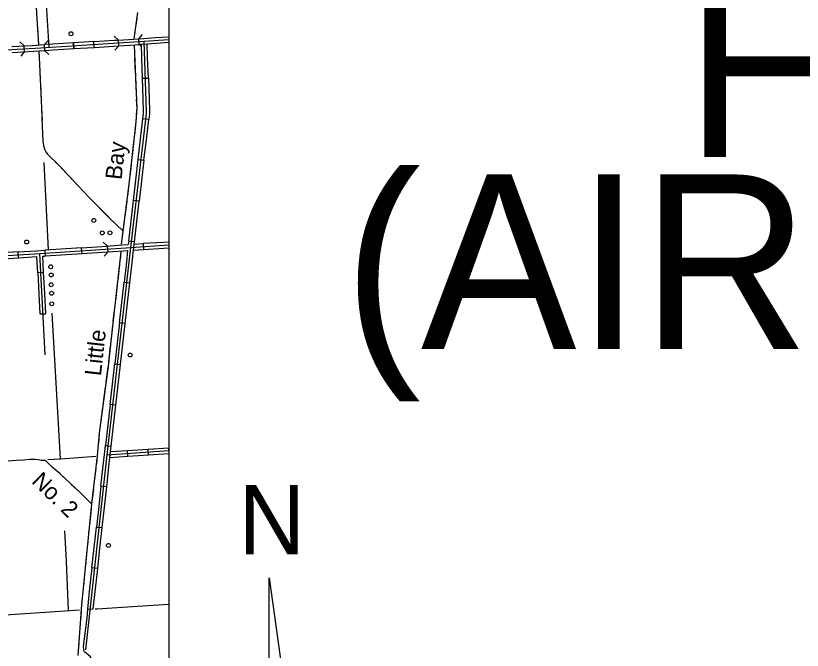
# Model space of a CAD drawing. Extents: x 309348 to 309445, y 336383 to 336484.
# Drawn here: x 309355.577 to 309359.624, y 336398.969 to 336402.233 of the extents above; entities that cross this region are included whole.
import ezdxf

# ---------------------------------------------------------------- set-up
doc = ezdxf.new("R2010")
doc.units = 0
doc.layers.add('R_Annotation', color=7, linetype='Continuous')
doc.layers.add('R_Border Notes', color=7, linetype='Continuous')

msp = doc.modelspace()

# ---------------------------------------------------------------- linework, layer by layer
at = {"layer": 'R_Annotation'}
for p, q in [((309356.107, 336402.0778), (309356.1051, 336402.1077)), ((309356.2116, 336402.0843), (309356.2097, 336402.1142)), ((309355.6221, 336402.0478), (309355.6203, 336402.0777)), ((309355.7231, 336402.0838), (309355.7248, 336402.0538)), ((309355.8754, 336402.0633), (309355.8735, 336402.0933)), ((309355.8735, 336402.0933), (309355.8754, 336402.0633)), ((309355.9808, 336402.0699), (309355.9789, 336402.0998)), ((309356.2106, 336402.0993), (309356.2106, 336402.0993)), ((309356.2116, 336402.0843), (309356.2116, 336402.0843)), ((309356.229, 336401.911), (309356.259, 336401.912)), ((309356.2611, 336401.6987), (309356.2313, 336401.7022)), ((309356.2068, 336401.4924), (309356.2366, 336401.4889)), ((309356.2122, 336401.2791), (309356.1824, 336401.2825)), ((309356.1877, 336401.0692), (309356.1579, 336401.0727)), ((309356.1828, 336401.0271), (309356.1863, 336401.0574)), ((309356.2321, 336401.0604), (309356.234, 336401.0304)), ((309355.5916, 336400.9879), (309355.5897, 336401.0178)), ((309355.8105, 336401.0322), (309355.7267, 336401.0266)), ((309355.7267, 336401.0266), (309355.7288, 336400.9973)), ((309355.9159, 336401.0393), (309355.8105, 336401.0322)), ((309355.9179, 336401.0093), (309355.9159, 336401.0393)), ((309356.0515, 336401.0183), (309356.0494, 336401.0483)), ((309356.0505, 336401.0333), (309356.0505, 336401.0333)), ((309355.7288, 336400.9973), (309355.9179, 336401.0093)), ((309355.72, 336400.9113), (309355.6901, 336400.9097)), ((309355.72, 336400.9113), (309355.72, 336400.9113)), ((309356.1339, 336400.8627), (309356.1637, 336400.8593)), ((309355.7013, 336400.6987), (309355.7312, 336400.7003)), ((309356.1398, 336400.6494), (309356.11, 336400.6528)), ((309356.0861, 336400.4429), (309356.1159, 336400.4395)), ((309356.092, 336400.2296), (309356.0622, 336400.233)), ((309356.092, 336400.2296), (309356.092, 336400.2296)), ((309356.0383, 336400.0231), (309356.0681, 336400.0197)), ((309356.2597, 336399.9738), (309356.2577, 336400.0037)), ((309356.3641, 336399.9968), (309356.3631, 336400.0108)), ((309356.1543, 336399.9668), (309356.1523, 336399.9967)), ((309356.0448, 336399.8097), (309356.015, 336399.813)), ((309355.9918, 336399.6031), (309356.0216, 336399.5998)), ((309355.9984, 336399.3898), (309355.9686, 336399.3931)), ((309356.8815, 336399.3417), (309357.1027, 336397.7428)), ((309356.8815, 336397.4244), (309356.8815, 336399.3417)), ((309355.9451, 336399.1806), (309355.9755, 336399.1826))]:
    msp.add_line(p, q, dxfattribs=at)
for points in [[(309355.6632, 336402.7078), (309355.679, 336402.3352), (309355.6875, 336402.1915), (309355.693, 336402.0854)], [(309355.7301, 336402.3468), (309355.7462, 336402.0701)], [(309356.2038, 336402.2495), (309356.1847, 336402.1141)], [(309355.6858, 336402.2198), (309355.6875, 336402.1915), (309355.6901, 336402.1407)], [(309356.1995, 336402.2191), (309356.1884, 336402.1406)], [(309354.9254, 336402.0215), (309355.1653, 336402.0358), (309355.7066, 336402.0678), (309356.2375, 336402.1009), (309356.3641, 336402.1095)], [(309355.6915, 336402.1143), (309355.693, 336402.0854)], [(309355.7231, 336402.0831), (309355.743, 336402.1056)], [(309355.9789, 336402.0998), (309356.0844, 336402.1064), (309356.1051, 336402.1077)], [(309356.0826, 336402.1276), (309356.1051, 336402.1077)], [(309356.1051, 336402.1077), (309356.2097, 336402.1142)], [(309356.1848, 336402.1145), (309356.1847, 336402.1141)], [(309356.2097, 336402.1142), (309356.2296, 336402.1367)], [(309356.2097, 336402.1142), (309356.2366, 336402.1159), (309356.2951, 336402.1199)], [(309356.2951, 336402.1199), (309356.3641, 336402.1245)], [(309355.5572, 336402.074), (309355.6627, 336402.0802)], [(309355.5979, 336402.0977), (309355.6203, 336402.0777)], [(309355.6627, 336402.0802), (309355.7231, 336402.0838)], [(309355.7681, 336402.0867), (309355.7231, 336402.0839)], [(309355.8735, 336402.0933), (309355.7681, 336402.0867)], [(309355.77, 336402.0567), (309355.8754, 336402.0633)], [(309355.9789, 336402.0998), (309355.8735, 336402.0933)], [(309355.8754, 336402.0633), (309355.9808, 336402.0699)], [(309355.9371, 336398.9714), (309356.0479, 336399.9747), (309356.1694, 336401.0413), (309356.2478, 336401.7142), (309356.2493, 336401.7307), (309356.2498, 336401.7404), (309356.2375, 336402.1009)], [(309355.9808, 336402.0699), (309356.107, 336402.0778)], [(309356.107, 336402.0778), (309356.0871, 336402.0553)], [(309356.107, 336402.0778), (309356.1917, 336402.083), (309356.2116, 336402.0843)], [(309356.1859, 336402.0808), (309356.199, 336401.7547), (309356.1947, 336401.6861), (309356.1593, 336401.3669), (309356.1286, 336401.1238), (309356.1196, 336401.0577)], [(309356.1859, 336402.0808), (309356.1875, 336402.0412)], [(309356.253, 336402.087), (309356.2231, 336402.085), (309356.2116, 336402.0843)], [(309356.2234, 336402.0738), (309356.2116, 336402.0843)], [(309356.2254, 336402.0165), (309356.2231, 336402.085)], [(309356.3641, 336402.0945), (309356.2972, 336402.0899), (309356.253, 336402.087)], [(309356.2554, 336402.0176), (309356.253, 336402.087)], [(309355.559, 336402.0441), (309355.725, 336402.0531)], [(309355.6221, 336402.0478), (309355.6022, 336402.0253)], [(309355.6949, 336402.0501), (309355.6984, 336401.9829), (309355.7095, 336401.7565), (309355.7129, 336401.6631), (309355.7169, 336401.585), (309355.7209, 336401.5585), (309355.7258, 336401.5437), (309355.7308, 336401.532), (309355.7397, 336401.5204), (309355.7981, 336401.4637), (309355.8979, 336401.3574), (309355.9569, 336401.2962), (309356.0574, 336401.1934), (309356.0985, 336401.1535), (309356.1223, 336401.131), (309356.1286, 336401.1238)], [(309355.6949, 336402.0501), (309355.6969, 336402.0106)], [(309355.7248, 336402.0539), (309355.77, 336402.0567)], [(309355.7475, 336402.0332), (309355.725, 336402.0531)], [(309355.6983, 336401.9842), (309355.6984, 336401.9829), (309355.7022, 336401.9051)], [(309356.1886, 336402.0148), (309356.1918, 336401.9357)], [(309356.229, 336401.911), (309356.2254, 336402.0165)], [(309356.259, 336401.912), (309356.2554, 336402.0176)], [(309356.1928, 336401.9093), (309356.196, 336401.8301)], [(309356.2326, 336401.8054), (309356.229, 336401.911)], [(309356.259, 336401.912), (309356.2626, 336401.8064)], [(309355.7035, 336401.8787), (309355.7073, 336401.7996)], [(309356.197, 336401.8037), (309356.199, 336401.7547), (309356.1971, 336401.7246)], [(309356.2313, 336401.7022), (309356.2329, 336401.7157), (309356.2343, 336401.7318), (309356.2348, 336401.7406), (309356.2326, 336401.8054)], [(309356.2626, 336401.8064), (309356.2649, 336401.7402), (309356.2642, 336401.7296), (309356.2627, 336401.7127), (309356.2611, 336401.6987)], [(309355.7086, 336401.7732), (309355.7095, 336401.7565), (309355.7118, 336401.694)], [(309356.2191, 336401.5973), (309356.2313, 336401.7022)], [(309356.2489, 336401.5938), (309356.2611, 336401.6987)], [(309355.7128, 336401.6676), (309355.7129, 336401.6631), (309355.7167, 336401.5885)], [(309356.1955, 336401.6983), (309356.1947, 336401.6861), (309356.1873, 336401.6195)], [(309356.1844, 336401.5932), (309356.1757, 336401.5145)], [(309356.2068, 336401.4924), (309356.2191, 336401.5973)], [(309356.2366, 336401.4889), (309356.2489, 336401.5938)], [(309355.7203, 336401.5623), (309355.7209, 336401.5585), (309355.7258, 336401.5437), (309355.7308, 336401.532), (309355.7397, 336401.5204), (309355.7629, 336401.4978)], [(309355.7453, 336401.0278), (309355.7226, 336401.477)], [(309355.7819, 336401.4794), (309355.7981, 336401.4637), (309355.8097, 336401.4513)], [(309356.1728, 336401.4882), (309356.1684, 336401.4489)], [(309356.1946, 336401.3875), (309356.2068, 336401.4924)], [(309356.2366, 336401.4889), (309356.2244, 336401.384)], [(309355.8097, 336401.4513), (309355.8369, 336401.4224)], [(309356.1684, 336401.4489), (309356.164, 336401.4095)], [(309355.8549, 336401.4032), (309355.8979, 336401.3574), (309355.9093, 336401.3456)], [(309356.1611, 336401.3832), (309356.1593, 336401.3669), (309356.1514, 336401.3046)], [(309356.1824, 336401.2825), (309356.1946, 336401.3875)], [(309356.2244, 336401.384), (309356.2122, 336401.2791)], [(309355.9276, 336401.3265), (309355.9569, 336401.2962), (309355.9828, 336401.2697)], [(309356.1481, 336401.2784), (309356.1382, 336401.1998)], [(309356.1701, 336401.1776), (309356.1824, 336401.2825)], [(309356.1999, 336401.1741), (309356.2122, 336401.2791)], [(309356.0013, 336401.2508), (309356.0567, 336401.1942)], [(309356.0756, 336401.1758), (309356.0985, 336401.1535), (309356.1223, 336401.131), (309356.1286, 336401.1238)], [(309356.1349, 336401.1736), (309356.1286, 336401.1238), (309356.1246, 336401.095)], [(309356.1579, 336401.0727), (309356.1701, 336401.1776)], [(309356.1877, 336401.0692), (309356.1999, 336401.1741)], [(309355.7274, 336400.4885), (309355.6998, 336401.0097), (309356.1694, 336401.0413), (309356.3641, 336401.0537)], [(309356.0213, 336401.0464), (309356.1267, 336401.0535)], [(309356.0494, 336401.0483), (309356.0268, 336401.068)], [(309356.1267, 336401.0535), (309356.1559, 336401.0554)], [(309356.1579, 336401.0727), (309356.1559, 336401.0554)], [(309356.1863, 336401.0574), (309356.1877, 336401.0692)], [(309356.1863, 336401.0574), (309356.2321, 336401.0604)], [(309356.3375, 336401.0671), (309356.2321, 336401.0604)], [(309356.3641, 336401.0688), (309356.3375, 336401.0671)], [(309355.5897, 336401.0178), (309355.4843, 336401.0112)], [(309355.5897, 336401.0178), (309355.684, 336401.0237), (309355.7267, 336401.0266)], [(309356.1182, 336401.018), (309356.0756, 336400.6521), (309356.0515, 336400.4308), (309356.0061, 336400.0861), (309355.9962, 336399.9684), (309355.9669, 336399.7219), (309355.9153, 336399.2024), (309355.8969, 336398.9428)], [(309355.9159, 336401.0393), (309356.0213, 336401.0464)], [(309355.9179, 336401.0093), (309356.0233, 336401.0164)], [(309356.0233, 336401.0164), (309356.1287, 336401.0235)], [(309356.0317, 336400.9957), (309356.0515, 336401.0183)], [(309356.1182, 336401.018), (309356.1136, 336400.9787)], [(309356.1287, 336401.0235), (309356.1524, 336401.0251)], [(309356.1524, 336401.0251), (309356.1459, 336400.9677)], [(309356.1757, 336400.9643), (309356.1828, 336401.0271)], [(309356.1828, 336401.0271), (309356.234, 336401.0304)], [(309356.234, 336401.0304), (309356.3395, 336401.0371)], [(309356.3395, 336401.0371), (309356.3641, 336401.0387)], [(309354.958, 336400.9656), (309355.2254, 336400.98), (309355.6998, 336401.0097)], [(309355.4862, 336400.9813), (309355.5916, 336400.9879)], [(309355.5916, 336400.9879), (309355.6856, 336400.9938)], [(309355.6901, 336400.9097), (309355.6856, 336400.9938)], [(309355.7156, 336400.9957), (309355.7289, 336400.9966)], [(309355.72, 336400.9113), (309355.7156, 336400.9957)], [(309356.1105, 336400.9524), (309356.1014, 336400.8737)], [(309356.1459, 336400.9677), (309356.1339, 336400.8627)], [(309356.1637, 336400.8593), (309356.1757, 336400.9643)], [(309355.6901, 336400.9097), (309355.6957, 336400.8042)], [(309355.7256, 336400.8058), (309355.72, 336400.9113)], [(309356.122, 336400.7578), (309356.1339, 336400.8627)], [(309356.1518, 336400.7544), (309356.1637, 336400.8593)], [(309356.0983, 336400.8475), (309356.0892, 336400.7688)], [(309355.6957, 336400.8042), (309355.7013, 336400.6987)], [(309355.7312, 336400.7003), (309355.7256, 336400.8058)], [(309356.0861, 336400.7426), (309356.077, 336400.6639)], [(309356.11, 336400.6528), (309356.122, 336400.7578)], [(309356.1398, 336400.6494), (309356.1518, 336400.7544)], [(309355.807, 336399.9545), (309355.764, 336400.7022)], [(309356.11, 336400.6528), (309356.0981, 336400.5479)], [(309356.1279, 336400.5445), (309356.1398, 336400.6494)], [(309356.074, 336400.6376), (309356.0655, 336400.5589)], [(309356.0626, 336400.5326), (309356.054, 336400.4539)], [(309356.0981, 336400.5479), (309356.0861, 336400.4429)], [(309356.1159, 336400.4395), (309356.1279, 336400.5445)], [(309356.0511, 336400.4276), (309356.0459, 336400.3883)], [(309356.0742, 336400.3379), (309356.0861, 336400.4429)], [(309356.104, 336400.3345), (309356.1159, 336400.4395)], [(309356.0459, 336400.3883), (309356.0407, 336400.3491)], [(309356.0373, 336400.3229), (309356.0269, 336400.2443)], [(309356.0622, 336400.233), (309356.0742, 336400.3379)], [(309356.092, 336400.2296), (309356.104, 336400.3345)], [(309356.0235, 336400.2182), (309356.0132, 336400.1396)], [(309356.0622, 336400.233), (309356.0503, 336400.128)], [(309356.0801, 336400.1246), (309356.092, 336400.2296)], [(309356.0503, 336400.128), (309356.0383, 336400.0231)], [(309356.0681, 336400.0197), (309356.0801, 336400.1246)], [(309356.0097, 336400.1134), (309356.0061, 336400.0861), (309356.0018, 336400.0346)], [(309355.9996, 336400.0083), (309355.9962, 336399.9684), (309355.9916, 336399.9295)], [(309356.0266, 336399.918), (309356.033, 336399.9764), (309356.0383, 336400.0231)], [(309356.0649, 336399.9909), (309356.0681, 336400.0197)], [(309356.1523, 336399.9967), (309356.2577, 336400.0037)], [(309356.2577, 336400.0037), (309356.3631, 336400.0108)], [(309356.3631, 336400.0108), (309356.3641, 336400.0108)], [(309355.807, 336399.9545), (309355.9892, 336399.9677)], [(309356.0479, 336399.9747), (309356.3641, 336399.9958)], [(309356.0564, 336399.9147), (309356.0615, 336399.9606), (309356.0649, 336399.9909)], [(309356.0615, 336399.9606), (309356.1543, 336399.9668)], [(309356.0649, 336399.9909), (309356.1523, 336399.9967)], [(309356.1543, 336399.9668), (309356.2597, 336399.9738)], [(309356.2597, 336399.9738), (309356.3641, 336399.9808)], [(309355.9669, 336399.7219), (309355.9057, 336399.7818), (309355.8581, 336399.8262), (309355.8049, 336399.8767), (309355.7648, 336399.9107), (309355.7305, 336399.9454), (309355.7081, 336399.9444), (309355.6945, 336399.9486), (309355.676, 336399.9506), (309355.6498, 336399.9502), (309355.6171, 336399.9464), (309355.5789, 336399.9451), (309355.4727, 336399.9366), (309355.325, 336399.9279), (309355.3014, 336399.9263)], [(309355.6737, 336399.9505), (309355.6498, 336399.9502), (309355.6171, 336399.9464), (309355.5948, 336399.9456)], [(309355.7643, 336399.9112), (309355.7305, 336399.9454), (309355.7081, 336399.9444), (309355.6998, 336399.947)], [(309355.742, 336399.9509), (309355.807, 336399.9545)], [(309356.015, 336399.813), (309356.0266, 336399.918)], [(309355.8429, 336399.8406), (309355.8049, 336399.8767), (309355.7845, 336399.8941)], [(309355.9884, 336399.9033), (309355.9791, 336399.8246)], [(309356.0448, 336399.8097), (309356.0564, 336399.9147)], [(309355.9197, 336399.7681), (309355.9057, 336399.7818), (309355.8621, 336399.8224)], [(309355.976, 336399.7984), (309355.9713, 336399.759)], [(309356.015, 336399.813), (309356.0034, 336399.708)], [(309356.0332, 336399.7048), (309356.0448, 336399.8097)], [(309355.9713, 336399.759), (309355.9669, 336399.7219), (309355.9667, 336399.7197)], [(309355.9669, 336399.7219), (309355.9386, 336399.7496)], [(309355.964, 336399.6934), (309355.9562, 336399.6146)], [(309356.0034, 336399.708), (309355.9918, 336399.6031)], [(309356.0216, 336399.5998), (309356.0332, 336399.7048)], [(309355.9802, 336399.4981), (309355.9918, 336399.6031)], [(309356.01, 336399.4948), (309356.0216, 336399.5998)], [(309355.8485, 336399.1742), (309355.8374, 336399.4281), (309355.8285, 336399.5837)], [(309355.9536, 336399.5883), (309355.9458, 336399.5095)], [(309355.9432, 336399.4832), (309355.9354, 336399.4043)], [(309355.9686, 336399.3931), (309355.9802, 336399.4981)], [(309355.9984, 336399.3898), (309356.01, 336399.4948)], [(309355.9686, 336399.3931), (309355.957, 336399.2881)], [(309355.9328, 336399.3781), (309355.9249, 336399.2992)], [(309355.9868, 336399.2848), (309355.9984, 336399.3898)], [(309355.9223, 336399.2729), (309355.9153, 336399.2024), (309355.9148, 336399.1941)], [(309355.957, 336399.2881), (309355.9451, 336399.1806)], [(309355.9755, 336399.1826), (309355.9868, 336399.2848)], [(309355.9855, 336399.1819), (309355.9962, 336399.1825), (309356.2031, 336399.1958), (309356.3641, 336399.2062)], [(309355.4407, 336399.1472), (309355.5476, 336399.154), (309355.7534, 336399.1671), (309355.9052, 336399.1768)], [(309355.9129, 336399.1677), (309355.9101, 336399.1282)], [(309355.9681, 336398.9169), (309355.9629, 336398.9324), (309355.9591, 336398.9364), (309355.9308, 336398.961), (309355.9279, 336398.9679), (309355.9265, 336398.9766), (309355.9259, 336398.987), (309355.9311, 336399.0301), (309355.9435, 336399.1354), (309355.9481, 336399.1808)], [(309355.9101, 336399.1282), (309355.9073, 336399.0887)], [(309355.9054, 336399.0624), (309355.8998, 336398.9833)]]:
    msp.add_lwpolyline(points, dxfattribs=at)
for centre in [(309355.861, 336402.1399), (309355.9784, 336401.1799), (309356.022, 336401.1158), (309356.0615, 336401.116), (309355.6328, 336401.0688), (309355.7566, 336400.9415), (309355.7593, 336400.8994), (309355.7591, 336400.8489), (309355.761, 336400.8053), (309355.7618, 336400.751), (309356.1656, 336400.4875), (309356.0535, 336399.5084)]:
    msp.add_circle(centre, 0.01, dxfattribs=at)
at = {"layer": 'R_Border Notes'}
msp.add_line((309356.3641, 336403.9877), (309356.3641, 336395.7269), dxfattribs=at)

# ---------------------------------------------------------------- texts
at = {"layer": 'R_Annotation'}
for s, height, p in [('HWY. 351 RR OVERPASS', 0.896903, (309359.0212, 336401.5059)), ('(AIRPORT RD.) (JONESBORO) (S)', 0.896903, (309357.2627, 336400.5194)), ('N', 0.3569, (309356.7224, 336399.4624))]:
    msp.add_text(s, height=height, dxfattribs=at).set_placement(p)
for s, rotation, p in [('Bay', 83.6847, (309356.121, 336401.3863)), ('Little', 83.6439, (309356.0148, 336400.3772)), ('No. 2', 315.9167, (309355.6539, 336399.833))]:
    msp.add_text(s, height=0.08451, rotation=rotation, dxfattribs=at).set_placement(p)

doc.saveas('drawing.dxf')
